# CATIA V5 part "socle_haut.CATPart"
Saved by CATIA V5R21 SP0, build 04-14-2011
Part number: socle_haut
Revision: A
Nomenclature: 4
Material "Blanc": density 7860 kg/m3, Young's modulus 2e+11 Pa, Poisson ratio 0.266
Bounding box of the stored display mesh (mm): x -22 to 22, y -70 to 42.5, z 0 to 62
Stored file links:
  C:\Users\Olivier\Desktop\redaction CATIA (local)\CATIA\DONNEES\Exercice assemblage 1 (chassis et socle)\socle_haut.CATPart
  C:\Program Files\Dassault Systemes\B21\win_b64\startup\materials\French\Catalog.CATMaterial
  C:\Users\Olivier\Desktop\redaction CATIA (local)\pompe à moteur de ventilation refait\Pompe_a_moteur_de_ventilation.CATProduct
  C:\Users\Olivier\Desktop\redaction CATIA (local)\pompe à moteur de ventilation refait\Ecrou a collerette M5.CATPart
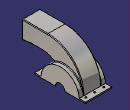
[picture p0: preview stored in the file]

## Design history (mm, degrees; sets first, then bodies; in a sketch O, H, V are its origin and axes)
Body1 (main body), material "Blanc"
  Sketch1 on yz-plane, origin (0, 0, 0), H (0, 1, 0), V (0, 0, 1)
    arc A1 centre (0, 0) radius 8 from (8, 0) to (-8, 0) ccw
    arc A2 centre (0, 0) radius 32 from (-16, 27.7128) to (-31.9374, 2) ccw
    point P1 (-42.5, 0)
    line L1 (-42.5, 0) -> (-8, 0)
    line L2 (42.5, 0) -> (42.5, 2)
    line L3 (42.5, 2) -> (32, 2)
    line L4 (-42.5, 2) -> (-42.5, 0)
    point P3 (42.5, 2)
    point P4 (-42.5, 2)
    point P6 (8, 0)
    line L5 (8, 0) -> (42.5, 0)
    line L6 (-31.9374, 2) -> (-42.5, 2)
    point P8 (32, 2)
    arc A3 centre (-28, 2) radius 60 from (32, 2) to (-28, 62) ccw
    line L7 (-28, 62) -> (-70, 62)
    point P11 (-70, 62)
    construction line L8 (0, 0) -> (-16, 27.7128)
    point P12 (-16, 27.7128)
    line L9 (-16, 27.7128) -> (-24.137, 31.367)
    point P13 (-16, 27.7128)
    point P14 (-30, 34)
    line L10 (-36.4271, 34) -> (-53.0088, 34)
    point P15 (-55, 34)
    line L11 (-56.9737, 33.7368) -> (-70, 32)
    point P16 (-70, 32)
    line L12 (-70, 32) -> (-70, 62)
    construction line L13 (32, 2) -> (32, 18.4391)
    arc A4 centre (0.0604, 0.035) radius 32 from (-16, 27.7128) to (32, 2) cw
    point P19 (-16, 27.7128)
    arc A5 centre (-53.0088, 4) radius 30 from (-53.0088, 34) to (-56.9737, 33.7368) ccw
    arc A6 centre (-36.4271, 4) radius 30 from (-24.137, 31.367) to (-36.4271, 34) ccw
    radius A1 = 8
    radius A2 = 32
    length L2 = 2
    distance P3 P4 = 85
    radius A3 = 60
    distance P11 V = 70
    distance P16 P11 = 30
    distance L10 L7 = 28
    distance P14 P16 H = 40
    angle L8 V = 30
    distance P8 V = 32
    radius A4 = 32
    distance P15 P16 H = 15
    radius A5 = 30
    radius A6 = 30
    coincidence: P1 H, L1 P6, L1 L5, L3 L6, P13 A2, P13 P12, A4 P19, P19 A2, L10 P15, L11 P15, L9 P14, L10 P14
    horizontal: L1 H, L3 H, L5 H, L6 H, L7 H, L10 H
    vertical: L2 V, L4 V, L12 V, L13 V
    symmetry: L2 L4 V
    tangency: A3 L7, L13 A3, A5 L10, A5 L11, A6 L9, A6 L10
  MultiPad1: profile Sketch1, domains (length 15 / length 15; length 22 / length 22)
  Sketch2 on yz-plane, origin (0, 0, 0), H (0, 1, 0), V (0, 0, 1)
    circle A1 centre (0, 0) radius 31
    radius A1 = 31
  Pocket1: profile Sketch2, direction (-1, 0, 0), length 21, mirrored extent
  Shell1: ExtOffset 0, Face (face of MultiPad1 from Sketch1.L12; face of Pocket1 from Sketch2.A1), IntOffset 1
  Sketch3 on face of MultiPad1 from Sketch1.L1, origin (12.1493, -36.3201, 0), H (1, 0, 0), V (0, -1, 0)
    point P1 (2.8507, -0.3201)
    reference projected line E1 through (0, -36.3201) direction (1, 0) from axis of face of Pocket1 from Sketch2.A1
    reference intersected line E2 through (-12.1493, 0) direction (0, 1) from yz-plane
    distance P1 E1 = 36
    distance P1 E2 = 15
  Hole1: placed by Sketch3, at (15, -36, 0) direction (0, 0, 1), diameter 3, through (limit type 6)
  RectPattern1: of Hole1, direction 1 instances 3, spacing 15, along edge [face of MultiPad1 from Sketch1.L1 | face of MultiPad1 from Sketch1.L4] reversed, direction 2 instances 2, spacing 72, along edge [face of MultiPad1 from Sketch1.L1 | face of MultiPad1]
  Fillet1: radius 1, on edge [face of MultiPad1 | face of MultiPad1 from Sketch1.L7]; edge [face of MultiPad1 from Sketch1.L7 | face of MultiPad1]; edge [face of MultiPad1 from Sketch1.L11 | face of MultiPad1]; edge [face of MultiPad1 | face of MultiPad1 from Sketch1.L9]; edge [face of MultiPad1 | face of MultiPad1 from Sketch1.A4]; edge [face of MultiPad1 from Sketch1.A2 | face of MultiPad1 from Sketch1.L9]; edge [face of MultiPad1 from Sketch1.A4 | face of MultiPad1]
